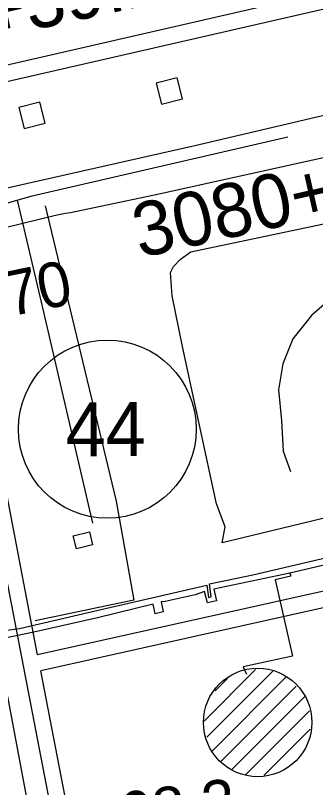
# Model space of a CAD drawing. Extents: x 3392644 to 3430565, y 576657 to 602123.
# Drawn here: x 3414763 to 3415320, y 586038 to 587469 of the extents above; entities that cross this region are included whole.
import ezdxf

# ---------------------------------------------------------------- set-up
doc = ezdxf.new("R2010")
doc.units = 0
for name, color, linetype in [('V-BLDG-OTLN', 7, 'Continuous'), ('V-DOMW-TANK', 7, 'Continuous'), ('V-RIVR-RANG-IDEN', 7, 'Continuous'), ('V-ROAD-CNTR', 7, 'Continuous'), ('V-ROAD-IDEN', 7, 'Continuous'), ('V-SITE-OTLN', 7, 'Continuous'), ('V-SURV-IDEN', 7, 'Continuous'), ('V-TOPO-SHOR', 7, 'Continuous'), ('V-UTIL-LINE', 7, 'Continuous')]:
    doc.layers.add(name, color=color, linetype=linetype)

msp = doc.modelspace()

# ---------------------------------------------------------------- linework, layer by layer
at = {"layer": 'V-BLDG-OTLN'}
for points in [[(3415063.3, 587353.3), (3415024.5, 587343.3), (3415034.6, 587304.6), (3415073.3, 587314.6)], [(3414808.4, 587308.5), (3414769.6, 587298.4), (3414779.6, 587259.7), (3414818.4, 587269.7)], [(3414870.7, 586504.4), (3414900.6, 586511.9), (3414906.6, 586488.3), (3414876.7, 586480.8)]]:
    msp.add_lwpolyline(points, close=True, dxfattribs=at)
at = {"layer": 'V-DOMW-TANK'}
for p, q in [((3415113.2, 586161.4), (3415208.8, 586257)), ((3415118.5, 586131.3), (3415240.8, 586253.6)), ((3415128.7, 586106.2), (3415265.6, 586243.1)), ((3415133.7, 586217.3), (3415156.9, 586240.4)), ((3415145, 586087.1), (3415284.1, 586226.3)), ((3415165.7, 586072.4), (3415300.7, 586207.5)), ((3415190.1, 586061.6), (3415308.7, 586180.1)), ((3415225, 586061.1), (3415310, 586146.1))]:
    msp.add_line(p, q, dxfattribs=at)
msp.add_circle((3415212.7, 586158.9), 100.6, dxfattribs=at)
at = {"layer": 'V-ROAD-CNTR'}
for points in [[(3414400.9, 587267.7), (3416388.7, 587722.8)], [(3414394.2, 587296.9), (3416231.3, 587717.6)], [(3414804.6, 586284.3), (3414714, 586753.6)], [(3414963.1, 585305), (3414684.5, 586747.9)], [(3416113.9, 586575.3), (3414804.6, 586284.3)], [(3416114, 586544.6), (3414810.3, 586254.8)], [(3414992.6, 585310.6), (3414810.3, 586254.8)]]:
    msp.add_lwpolyline(points, dxfattribs=at)
at = {"layer": 'V-ROAD-IDEN'}
msp.add_circle((3414933.8, 586702.4), 165, dxfattribs=at)
msp.add_circle((3414933.8, 586702.4), 165, dxfattribs=at)
at = {"layer": 'V-SITE-OTLN'}
msp.add_lwpolyline([(3416164.3, 584550.7), (3416161.1, 584568), (3416097, 584831.4), (3415528, 584706.7), (3415441.1, 585124.8), (3414885.8, 585003.9), (3414787.6, 585534.1), (3414674, 586142.1), (3414579.1, 586564.1), (3414488.4, 587013.5), (3414833, 587097.6), (3414846.4, 587100.5), (3414856, 587102.4), (3414865.5, 587103.9), (3415026.6, 587138), (3415544.3, 587252.4), (3415572.5, 587260.1), (3415594.5, 587264.5), (3415667.1, 587280.6), (3416201.5, 587400.8), (3417016.1, 587577.2)], dxfattribs=at)
at = {"layer": 'V-TOPO-SHOR'}
for points in [[(3416334.9, 587706.8), (3416426.5, 587726), (3416467.6, 587564.3), (3416464.9, 587545.4), (3416103.8, 587457.8), (3415330.4, 587282.4), (3415095.9, 587227.6), (3414476.1, 587087.8), (3414454.3, 587130.8), (3414432.5, 587209), (3414424.2, 587260.2)], [(3414476.2, 587058.1), (3414651.4, 587093.8), (3414794.2, 587134.8), (3415268.5, 587244.4)], [(3414907, 586528.3), (3414816.5, 586916.4), (3414767.2, 587126.6)], [(3415349.3, 586540.7), (3415147.1, 586491.4), (3415152.4, 586521.1), (3415136.1, 586564.2), (3415073, 586855.3), (3415053.8, 586949.6), (3415050.9, 586992.8), (3415056.3, 587003.6), (3415069.7, 587017.1), (3415088.5, 587030.7), (3415544, 587126.7)], [(3414818.5, 587116), (3414950, 586568.9), (3414983, 586385.6), (3414799.7, 586347.2)], [(3415355.9, 586950.7), (3415312.8, 586912.8), (3415277.9, 586869.5), (3415259.2, 586823.6), (3415251.3, 586775), (3415256.9, 586718.4), (3415259.8, 586661.8), (3415273.4, 586624)]]:
    msp.add_lwpolyline(points, dxfattribs=at)
at = {"layer": 'V-UTIL-LINE'}
for points in [[(3414705.8, 586321), (3414733.5, 586328.1), (3414771.1, 586333), (3414917.1, 586367.1), (3415118.4, 586413.5), (3415121.6, 586390.5), (3415126.4, 586391.5), (3415123.2, 586415.5), (3415203.9, 586432.2), (3415391.1, 586476.5), (3415513.8, 586503.7), (3415469, 586698.9)], [(3415359.8, 586456.1), (3415272.4, 586435.3), (3415131.7, 586405.9), (3415136.4, 586384), (3415119.7, 586380.5), (3415114.3, 586401.5), (3415096.8, 586395.3), (3415041.3, 586382.7), (3415033.7, 586382.3), (3415037.7, 586363.6), (3415022.5, 586360.1), (3415018.8, 586378.3), (3414915.4, 586353), (3414797.5, 586326.4), (3414731.1, 586312.5)], [(3415272.4, 586435.3), (3415274, 586429.8), (3415245, 586423.4), (3415277.3, 586281.4), (3415185.6, 586262.2), (3415191.8, 586248.5)], [(3414748.9, 586207.2), (3414831.3, 585765), (3414934.3, 585199.3), (3414951, 585115), (3415354.5, 585207.7), (3415760.9, 585305.2), (3415759.7, 585314.1), (3415652.8, 585293.8), (3415634.4, 585364.5), (3415644.7, 585367.7), (3415659.8, 585302.5), (3415735.9, 585319.4), (3415731.5, 585341.4), (3416082.4, 585422.3), (3416225.2, 585455.5)]]:
    msp.add_lwpolyline(points, dxfattribs=at)

# ---------------------------------------------------------------- texts
at = {"layer": 'V-RIVR-RANG-IDEN'}
for s, rotation, p in [('D-070', 11.5338, (3414577.1, 586875)), ('R-168.3', 7.624, (3414785.1, 585921.3))]:
    msp.add_text(s, height=83, rotation=rotation, dxfattribs=at).set_placement(p)
at = {"layer": 'V-ROAD-IDEN'}
msp.add_text('44', height=100, rotation=0.2083, dxfattribs=at).set_placement((3414856.5, 586652.1))
at = {"layer": 'V-SURV-IDEN'}
for s, rotation, p in [('3076+39.2', 12.2752, (3414423.4, 587360.8)), ('3080+85.3', 12.6574, (3414994, 587019.2))]:
    msp.add_text(s, height=100, rotation=rotation, dxfattribs=at).set_placement(p)

doc.saveas('drawing.dxf')
